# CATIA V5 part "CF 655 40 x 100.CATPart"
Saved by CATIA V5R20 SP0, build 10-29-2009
Part number: CF 655 40 x 100
Definition: NONE
Nomenclature: CF 655 40 x 100
Source: Unknown
Description: CF 655 40 x 100
Bounding box of the stored display mesh (mm): x -70 to 30, y -31.5 to 31.5, z -31.5 to 31.5
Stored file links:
  C:\Users\Utente\Desktop\IO LAVORO\3D X SITO CF\X SITO\CF 655\CF 655 40 x 100.CATPart
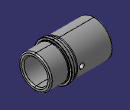
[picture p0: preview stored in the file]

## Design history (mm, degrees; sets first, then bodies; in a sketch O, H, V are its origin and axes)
Body1 "CF 655 40 x 100" (main body)
  Solid1: solid without history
